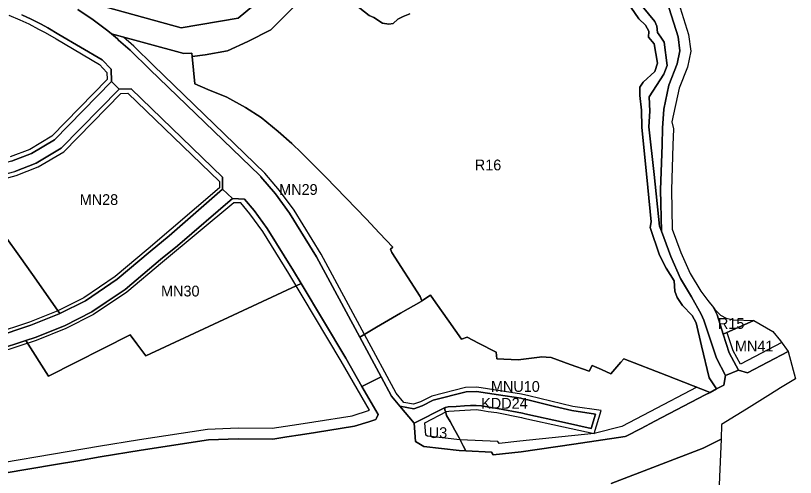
# Model space of a CAD drawing. Extents: x 7440055 to 7442242, y 5549003 to 5552256.
# Drawn here: x 7441405 to 7442129, y 5549663 to 5550092 of the extents above; entities that cross this region are included whole.
import ezdxf

# ---------------------------------------------------------------- set-up
doc = ezdxf.new("R2010")
doc.units = 0
for name, color, linetype in [('linie_rozgraniczajace', 7, 'Continuous'), ('linie_zabudowy_nieprzekraczalne', 7, 'Continuous'), ('oznaczenia_przeznaczen', 7, 'Continuous')]:
    doc.layers.add(name, color=color, linetype=linetype)

msp = doc.modelspace()

# ---------------------------------------------------------------- linework, layer by layer
at = {"layer": 'linie_rozgraniczajace'}
for points in [[(7441674.24, 5550141.39), (7441611.9, 5550089.62), (7441559.01, 5550080.87), (7441481.52, 5550102.04)], [(7441559.01, 5550080.87), (7441611.9, 5550089.62), (7441674.24, 5550141.39)], [(7441692.73, 5550130), (7441642.28, 5550079.02), (7441620.77, 5550068.05), (7441601.87, 5550059.51), (7441581.34, 5550055.76), (7441569.05, 5550054.15), (7441568.76, 5550057.15), (7441561.3, 5550056.89), (7441494.21, 5550075.16), (7441490.83, 5550078.03), (7441477.25, 5550088.28), (7441463.14, 5550097.77)], [(7441972.94, 5550105.02), (7441983.93, 5550089.01), (7441990.13, 5550083.21), (7441993.12, 5550077.7), (7441993.01, 5550072.24), (7441998.22, 5550065.89), (7442001.21, 5550048.12), (7441998.6, 5550040.12), (7441988.07, 5550030.45), (7441984.77, 5550025.7), (7441984.94, 5550018.04), (7441986.35, 5550004.2), (7441986.75, 5549988.5), (7441992.16, 5549932.41), (7441995.23, 5549900.66), (7441994.44, 5549895.25), (7442003.03, 5549869.81), (7442009.41, 5549857.55), (7442016.6, 5549845.99), (7442017.41, 5549836.2), (7442019.5, 5549830.32), (7442024.59, 5549822.88), (7442033.53, 5549813.67), (7442037.16, 5549806.8), (7442042.16, 5549785.37), (7442049.07, 5549755.74), (7442056.11, 5549745.53), (7442050, 5549742.32), (7442010.03, 5549757.96), (7441970.05, 5549773.59), (7441967.06, 5549770.5), (7441957.87, 5549759.65), (7441949.26, 5549763.47), (7441940.66, 5549767.29), (7441937.79, 5549761.95), (7441920.15, 5549768.26), (7441902.51, 5549774.58), (7441897.92, 5549774.87), (7441893.33, 5549775.16), (7441891.75, 5549774.94), (7441871.89, 5549772.55), (7441852.02, 5549773.37), (7441851.51, 5549779.71), (7441835.18, 5549787.99), (7441824.6, 5549793.62), (7441819.19, 5549791.62), (7441807.34, 5549808.48), (7441795.49, 5549825.34), (7441790.46, 5549832.53), (7441782.55, 5549827.29), (7441780.89, 5549831.28), (7441754.71, 5549872.13), (7441753.32, 5549875.41), (7441755.57, 5549877.22), (7441743.16, 5549890.27), (7441730.76, 5549903.32), (7441693.28, 5549942.22), (7441670.71, 5549964.67), (7441661.77, 5549973.45), (7441649.09, 5549984.53), (7441633.37, 5549997.39), (7441618.76, 5550006.86), (7441601.47, 5550016.57), (7441583.79, 5550023.49), (7441571.52, 5550028.92), (7441570.28, 5550041.54), (7441569.05, 5550054.15), (7441581.34, 5550055.76), (7441601.87, 5550059.51), (7441620.77, 5550068.05), (7441642.28, 5550079.02), (7441692.73, 5550130)], [(7441976.67, 5550113.66), (7441998.68, 5550086.75), (7442000.54, 5550082.2), (7442001.11, 5550076.43), (7442004.32, 5550072.02), (7442007.52, 5550067.62), (7442010.34, 5550045.8), (7442007.13, 5550037.86), (7441993.54, 5550016.61), (7441994.23, 5550003.51), (7441993.07, 5549988.97), (7441998.01, 5549944.73), (7442003.2, 5549896.54), (7442005.05, 5549891.87), (7442013.57, 5549868.39), (7442022.72, 5549848.18), (7442032.85, 5549831.05), (7442041.65, 5549815.05), (7442044.4, 5549809.39), (7442055.87, 5549774.01), (7442064.47, 5549758.06), (7442062.89, 5549749.08), (7442056.11, 5549745.53), (7442049.07, 5549755.74), (7442042.16, 5549785.37), (7442037.16, 5549806.8), (7442033.53, 5549813.67), (7442024.59, 5549822.88), (7442019.5, 5549830.32), (7442017.41, 5549836.2), (7442016.6, 5549845.99), (7442009.41, 5549857.55), (7442003.03, 5549869.81), (7441994.44, 5549895.25), (7441995.23, 5549900.66), (7441992.16, 5549932.41), (7441986.75, 5549988.5), (7441986.35, 5550004.2), (7441984.94, 5550018.04), (7441984.77, 5550025.7), (7441988.07, 5550030.45), (7441998.6, 5550040.12), (7442001.21, 5550048.12), (7441998.22, 5550065.89), (7441993.01, 5550072.24), (7441993.12, 5550077.7), (7441990.13, 5550083.21), (7441983.93, 5550089.01), (7441972.94, 5550105.02)], [(7442009.89, 5550105.65), (7442020.35, 5550072.34), (7442022, 5550059.49), (7442019.49, 5550047.24), (7442011.85, 5550027.55), (7442007.09, 5550005.31), (7442005.97, 5549987.77), (7442005.55, 5549972.04), (7442004.11, 5549930.49), (7442005.05, 5549891.87), (7442003.2, 5549896.54), (7441998.01, 5549944.73), (7441993.07, 5549988.97), (7441994.23, 5550003.51), (7441993.54, 5550016.61), (7442007.13, 5550037.86), (7442010.34, 5550045.8), (7442007.52, 5550067.62), (7442004.32, 5550072.02), (7442001.11, 5550076.43), (7442000.54, 5550082.2), (7441998.68, 5550086.75), (7441976.67, 5550113.66)], [(7442019.12, 5550109.63), (7442030.16, 5550074.49), (7442032.13, 5550059.11), (7442029.11, 5550044.41), (7442021.46, 5550024.67), (7442014.53, 5549993.6), (7442015.95, 5549987.13), (7442015.54, 5549971.73), (7442014.83, 5549951.09), (7442014.12, 5549930.44), (7442015, 5549893.75), (7442022.83, 5549872.17), (7442031.61, 5549852.8), (7442041.46, 5549836.15), (7442048, 5549827.75), (7442053.12, 5549821.19), (7442056.49, 5549814.25), (7442062.26, 5549796.46), (7442067.88, 5549779.14), (7442076.54, 5549763.06), (7442064.47, 5549758.06), (7442055.87, 5549774.01), (7442044.4, 5549809.39), (7442041.65, 5549815.05), (7442032.85, 5549831.05), (7442022.72, 5549848.18), (7442013.57, 5549868.39), (7442005.05, 5549891.87), (7442004.11, 5549930.49), (7442005.55, 5549972.04), (7442005.97, 5549987.77), (7442007.09, 5550005.31), (7442011.85, 5550027.55), (7442019.49, 5550047.24), (7442022, 5550059.49), (7442020.35, 5550072.34), (7442009.89, 5550105.65)], [(7441411.06, 5550092.87), (7441419.58, 5550088.95), (7441428.98, 5550084.13), (7441435.04, 5550080.83), (7441445.51, 5550074.75), (7441485.64, 5550051.12), (7441493.91, 5550042.46), (7441494.16, 5550031.09), (7441441.35, 5549976.89), (7441420.1, 5549964.26), (7441401.34, 5549957.05), (7441382.54, 5549951.99), (7441363.61, 5549950.18), (7441351.43, 5549950.16), (7441322.11, 5549991.27), (7441305.11, 5550015.41), (7441288.11, 5550039.55), (7441272.75, 5550061.72), (7441257.4, 5550083.89), (7441244.66, 5550101.57)], [(7441463.14, 5550097.77), (7441477.25, 5550088.28), (7441490.83, 5550078.03), (7441494.21, 5550075.16), (7441499.77, 5550070.46), (7441500.88, 5550069.36), (7441511.72, 5550060.01), (7441529.91, 5550042.11), (7441632, 5549943.59), (7441632.49, 5549943.12), (7441632.97, 5549942.66), (7441633, 5549942.63), (7441633.03, 5549942.59), (7441646.41, 5549926.57), (7441659.68, 5549908.55), (7441684.68, 5549868.19), (7441724.84, 5549793.66), (7441744.73, 5549756.72), (7441726.85, 5549747.85), (7441711.71, 5549773.91), (7441670.25, 5549843.55), (7441663.31, 5549855.21), (7441638.95, 5549894.53), (7441626.73, 5549911.13), (7441617.9, 5549921.71), (7441606.51, 5549922.31), (7441597.49, 5549930.9), (7441597.49, 5549942.15), (7441512.47, 5550024.21), (7441501.33, 5550023.93), (7441494.16, 5550031.09), (7441493.91, 5550042.46), (7441485.64, 5550051.12), (7441445.51, 5550074.75), (7441435.04, 5550080.83), (7441428.98, 5550084.13), (7441419.58, 5550088.95), (7441411.06, 5550092.87)], [(7441481.52, 5550102.04), (7441559.01, 5550080.87)], [(7441771.31, 5550093.94), (7441765.12, 5550091.38), (7441760.26, 5550088.83), (7441755.76, 5550084.91), (7441751.84, 5550084.12), (7441745.89, 5550085.02), (7441737.76, 5550090.54), (7441733.44, 5550092.16), (7441720.4, 5550102.47)], [(7441720.4, 5550102.47), (7441733.44, 5550092.16), (7441737.76, 5550090.54), (7441745.89, 5550085.02), (7441751.84, 5550084.12), (7441755.76, 5550084.91), (7441760.26, 5550088.83), (7441765.12, 5550091.38), (7441771.31, 5550093.94)], [(7441401.34, 5549957.05), (7441420.1, 5549964.26), (7441441.35, 5549976.89), (7441494.16, 5550031.09), (7441501.33, 5550023.93), (7441447.59, 5549968.97), (7441424.48, 5549955.23), (7441404.44, 5549947.53)], [(7441384.91, 5549793.35), (7441419.28, 5549804.6), (7441445.61, 5549815.19), (7441446.19, 5549815.48), (7441470.08, 5549827.43), (7441499.57, 5549847.44), (7441530.17, 5549873.25), (7441547.82, 5549887.51), (7441597.49, 5549930.9), (7441606.51, 5549922.31), (7441555.55, 5549878.33), (7441539.85, 5549865.65), (7441506.83, 5549837.87), (7441489.36, 5549826.01), (7441476.16, 5549817.06), (7441450.54, 5549804.24), (7441423.39, 5549793.32), (7441414.65, 5549790.45), (7441388.23, 5549781.81)], [(7441395.68, 5549887.23), (7441408.82, 5549868.65), (7441420.8, 5549851.6), (7441446.19, 5549815.48), (7441445.61, 5549815.19), (7441419.28, 5549804.6), (7441384.91, 5549793.35)], [(7441388.23, 5549781.81), (7441414.65, 5549790.45), (7441435.92, 5549757.3), (7441511.7, 5549795.71), (7441517.89, 5549787.47), (7441526.2, 5549776.27), (7441670.25, 5549843.55), (7441711.71, 5549773.91), (7441726.85, 5549747.85), (7441741.99, 5549721.79), (7441740.32, 5549718.3), (7441739.77, 5549717.16), (7441733.22, 5549715.09), (7441719.97, 5549710.88), (7441683.7, 5549704.98), (7441669.66, 5549702.95), (7441656.92, 5549700.93), (7441644.19, 5549698.91), (7441611.87, 5549699.24), (7441584.47, 5549698.28), (7441521.94, 5549688.54), (7441483.91, 5549682.43), (7441463.06, 5549678.85), (7441442.22, 5549675.26), (7441394.72, 5549667.37)], [(7441394.72, 5549667.37), (7441442.22, 5549675.26), (7441463.06, 5549678.85), (7441483.91, 5549682.43), (7441521.94, 5549688.54), (7441584.47, 5549698.28), (7441611.87, 5549699.24), (7441644.19, 5549698.91), (7441656.92, 5549700.93), (7441669.66, 5549702.95), (7441683.7, 5549704.98), (7441719.97, 5549710.88), (7441733.22, 5549715.09), (7441739.77, 5549717.16), (7441740.32, 5549718.3), (7441741.99, 5549721.79), (7441726.85, 5549747.85), (7441744.73, 5549756.72), (7441754.33, 5549738.88), (7441762.04, 5549729.6), (7441775.29, 5549713.56), (7441776.39, 5549696.69), (7441784.32, 5549691.97), (7441817.04, 5549688.22), (7441823.32, 5549687.94), (7441847.16, 5549686.89), (7441848.62, 5549684.33), (7441874.77, 5549687.08), (7441923.61, 5549694.24), (7441971.21, 5549701.23), (7441972.08, 5549701.49), (7441985.98, 5549708.77), (7441998.85, 5549715.52), (7442045.37, 5549739.9), (7442050, 5549742.32), (7442056.11, 5549745.53), (7442062.89, 5549749.08), (7442064.47, 5549758.06), (7442076.54, 5549763.06), (7442084.77, 5549760.55), (7442122.42, 5549780.28), (7442129.27, 5549755.01), (7442115.49, 5549746.43), (7442106.1, 5549740.59), (7442083.82, 5549726.72), (7442074.17, 5549720.9), (7442060.76, 5549712.39), (7442060.22, 5549698.83), (7442043.62, 5549690.55), (7441958.36, 5549657.75)], [(7441958.36, 5549657.75), (7442043.62, 5549690.55), (7442060.22, 5549698.83), (7442058.8, 5549663.73), (7442057.24, 5549624.99)]]:
    msp.add_lwpolyline(points, dxfattribs=at)
for points in [[(7441494.21, 5550075.16), (7441561.3, 5550056.89), (7441568.76, 5550057.15), (7441569.05, 5550054.15), (7441570.28, 5550041.54), (7441571.52, 5550028.92), (7441583.79, 5550023.49), (7441601.47, 5550016.57), (7441618.76, 5550006.86), (7441633.37, 5549997.39), (7441649.09, 5549984.53), (7441661.77, 5549973.45), (7441670.71, 5549964.67), (7441693.28, 5549942.22), (7441730.76, 5549903.32), (7441743.16, 5549890.27), (7441755.57, 5549877.22), (7441753.32, 5549875.41), (7441754.71, 5549872.13), (7441780.89, 5549831.28), (7441782.55, 5549827.29), (7441781.82, 5549826.81), (7441762.61, 5549815.72), (7441740.2, 5549802.86), (7441724.84, 5549793.66), (7441684.68, 5549868.19), (7441659.68, 5549908.55), (7441646.41, 5549926.57), (7441633.03, 5549942.59), (7441633, 5549942.63), (7441632.97, 5549942.66), (7441632.49, 5549943.12), (7441632, 5549943.59), (7441529.91, 5550042.11), (7441511.72, 5550060.01), (7441500.88, 5550069.36), (7441499.77, 5550070.46)], [(7441358.42, 5549940.18), (7441364.1, 5549940.19), (7441384.33, 5549942.11), (7441404.44, 5549947.53), (7441424.48, 5549955.23), (7441447.59, 5549968.97), (7441501.33, 5550023.93), (7441512.47, 5550024.21), (7441597.49, 5549942.15), (7441597.49, 5549930.9), (7441547.82, 5549887.51), (7441530.17, 5549873.25), (7441499.57, 5549847.44), (7441470.08, 5549827.43), (7441446.19, 5549815.48), (7441420.8, 5549851.6), (7441408.82, 5549868.65), (7441395.68, 5549887.23), (7441382.53, 5549905.82)], [(7441414.65, 5549790.45), (7441423.39, 5549793.32), (7441450.54, 5549804.24), (7441476.16, 5549817.06), (7441489.36, 5549826.01), (7441506.83, 5549837.87), (7441539.85, 5549865.65), (7441555.55, 5549878.33), (7441606.51, 5549922.31), (7441617.9, 5549921.71), (7441626.73, 5549911.13), (7441638.95, 5549894.53), (7441663.31, 5549855.21), (7441670.25, 5549843.55), (7441526.2, 5549776.27), (7441517.89, 5549787.47), (7441511.7, 5549795.71), (7441435.92, 5549757.3)], [(7441724.84, 5549793.66), (7441740.2, 5549802.86), (7441762.61, 5549815.72), (7441781.82, 5549826.81), (7441782.55, 5549827.29), (7441790.46, 5549832.53), (7441795.49, 5549825.34), (7441807.34, 5549808.48), (7441819.19, 5549791.62), (7441824.6, 5549793.62), (7441835.18, 5549787.99), (7441851.51, 5549779.71), (7441852.02, 5549773.37), (7441871.89, 5549772.55), (7441891.75, 5549774.94), (7441893.33, 5549775.16), (7441897.92, 5549774.87), (7441902.51, 5549774.58), (7441920.15, 5549768.26), (7441937.79, 5549761.95), (7441940.66, 5549767.29), (7441949.26, 5549763.47), (7441957.87, 5549759.65), (7441967.06, 5549770.5), (7441970.05, 5549773.59), (7442010.03, 5549757.96), (7442050, 5549742.32), (7442045.37, 5549739.9), (7441998.85, 5549715.52), (7441985.98, 5549708.77), (7441972.08, 5549701.49), (7441971.21, 5549701.23), (7441923.61, 5549694.24), (7441874.77, 5549687.08), (7441848.62, 5549684.33), (7441847.16, 5549686.89), (7441823.32, 5549687.94), (7441820.79, 5549692.75), (7441816.95, 5549700.05), (7441813.1, 5549707.34), (7441808.7, 5549715.11), (7441805.46, 5549720.8), (7441804.64, 5549723.51), (7441803.82, 5549726.22), (7441803.89, 5549727.2), (7441803.95, 5549728.18), (7441806.73, 5549728.94), (7441814.42, 5549729.33), (7441822.11, 5549729.71), (7441827.52, 5549729.99), (7441832.93, 5549730.26), (7441837.76, 5549729.86), (7441841.28, 5549729.16), (7441844.81, 5549728.45), (7441852.57, 5549727.42), (7441875.86, 5549723), (7441878.06, 5549722.3), (7441914.84, 5549714.19), (7441939.71, 5549708.72), (7441943.65, 5549722.12), (7441921.75, 5549725.37), (7441905.59, 5549729.27), (7441880.8, 5549735.26), (7441877.53, 5549736.04), (7441874.26, 5549736.83), (7441853.74, 5549739.91), (7441833.22, 5549742.98), (7441823.63, 5549742.8), (7441793.09, 5549735.04), (7441782.7, 5549729.87), (7441775.04, 5549727.15), (7441762.04, 5549729.6), (7441754.33, 5549738.88), (7441744.73, 5549756.72)], [(7442053.12, 5549821.19), (7442054.55, 5549819.35), (7442059.77, 5549813.9), (7442064.94, 5549811.12), (7442071.85, 5549809.55), (7442090.8, 5549809.16), (7442062.26, 5549796.46), (7442056.49, 5549814.25)], [(7442062.26, 5549796.46), (7442090.8, 5549809.16), (7442108.2, 5549798.8), (7442115.46, 5549790.27), (7442122.42, 5549780.28), (7442084.77, 5549760.55), (7442076.54, 5549763.06), (7442067.88, 5549779.14)], [(7441762.04, 5549729.6), (7441775.04, 5549727.15), (7441782.7, 5549729.87), (7441793.09, 5549735.04), (7441823.63, 5549742.8), (7441833.22, 5549742.98), (7441853.74, 5549739.91), (7441874.26, 5549736.83), (7441877.53, 5549736.04), (7441880.8, 5549735.26), (7441905.59, 5549729.27), (7441921.75, 5549725.37), (7441943.65, 5549722.12), (7441939.71, 5549708.72), (7441914.84, 5549714.19), (7441878.06, 5549722.3), (7441875.86, 5549723), (7441852.57, 5549727.42), (7441844.81, 5549728.45), (7441841.28, 5549729.16), (7441837.76, 5549729.86), (7441832.93, 5549730.26), (7441827.52, 5549729.99), (7441822.11, 5549729.71), (7441814.42, 5549729.33), (7441806.73, 5549728.94), (7441803.95, 5549728.18), (7441775.29, 5549713.56)], [(7441775.29, 5549713.56), (7441803.95, 5549728.18), (7441803.89, 5549727.2), (7441803.82, 5549726.22), (7441804.64, 5549723.51), (7441805.46, 5549720.8), (7441808.7, 5549715.11), (7441813.1, 5549707.34), (7441816.95, 5549700.05), (7441820.79, 5549692.75), (7441823.32, 5549687.94), (7441817.04, 5549688.22), (7441784.32, 5549691.97), (7441776.39, 5549696.69)]]:
    msp.add_lwpolyline(points, close=True, dxfattribs=at)
at = {"layer": 'linie_zabudowy_nieprzekraczalne'}
for points in [[(7441399, 5550092.55), (7441409.04, 5550088.3), (7441417.39, 5550084.45), (7441426.64, 5550079.71), (7441432.58, 5550076.47), (7441442.98, 5550070.44), (7441483.1, 5550046.81), (7441489.98, 5550039.34), (7441490.13, 5550032.68), (7441438.86, 5549980.06), (7441418.35, 5549967.87), (7441400.1, 5549960.86)], [(7442037.66, 5549747.15), (7441994.21, 5549724.38), (7441968.18, 5549710.73), (7441942.5, 5549704.01), (7441873.52, 5549697), (7441854.07, 5549694.96), (7441853.11, 5549696.64), (7441817.83, 5549698.19), (7441787.59, 5549701.66), (7441786.03, 5549702.59), (7441785.27, 5549714.16), (7441805.4, 5549724.43), (7441807.37, 5549724.97), (7441822.31, 5549725.72), (7441832.86, 5549726.25), (7441837.2, 5549725.89), (7441844.15, 5549724.51), (7441851.93, 5549723.47), (7441874.88, 5549719.11), (7441877.02, 5549718.43), (7441913.98, 5549710.29), (7441942.5, 5549704.01), (7441948.78, 5549725.4), (7441922.52, 5549729.3), (7441881.74, 5549739.14), (7441875.03, 5549740.76), (7441833.48, 5549746.99), (7441823.1, 5549746.79), (7441791.69, 5549738.81), (7441781.13, 5549733.56), (7441774.72, 5549731.28), (7441765.56, 5549732.78), (7441758.52, 5549741.64), (7441729.24, 5549796.04), (7441689.01, 5549870.69), (7441663.82, 5549911.35), (7441650.35, 5549929.65), (7441636.7, 5549946), (7441533.4, 5550045.69), (7441515.11, 5550063.69), (7441505.36, 5550072.13)], [(7441385.04, 5549938.16), (7441405.68, 5549943.72), (7441426.23, 5549951.62), (7441450.09, 5549965.8), (7441503.06, 5550019.97), (7441509.49, 5550020.13), (7441594.44, 5549938.15), (7441594.49, 5549932.28), (7441528.23, 5549875.53), (7441497.76, 5549849.84), (7441468.56, 5549830.03), (7441444.38, 5549817.93), (7441418.25, 5549807.42), (7441384.08, 5549796.23)], [(7441393.09, 5549677.24), (7441440.55, 5549685.12), (7441482.27, 5549692.3), (7441520.38, 5549698.42), (7441583.52, 5549708.25), (7441611.74, 5549709.24), (7441643.45, 5549708.92), (7441668.16, 5549712.84), (7441682.19, 5549714.86), (7441717.64, 5549720.63), (7441733.88, 5549725.79), (7441707.4, 5549771.37), (7441659.04, 5549852.61), (7441634.81, 5549891.73), (7441622.8, 5549908.05), (7441614.21, 5549918.28), (7441607.97, 5549918.3), (7441541.78, 5549863.35), (7441508.64, 5549835.47), (7441477.68, 5549814.46), (7441451.77, 5549801.51), (7441424.42, 5549790.5), (7441389.06, 5549778.93)], [(7442116.66, 5549788.55), (7442078.2, 5549768.4), (7442071.57, 5549780.72), (7442066.06, 5549797.7)]]:
    msp.add_lwpolyline(points, dxfattribs=at)

# ---------------------------------------------------------------- texts
at = {"layer": 'oznaczenia_przeznaczen'}
for s, p in [('R16', (7441831.64, 5549948.46)), ('MN29', (7441649.97, 5549925.69)), ('MN28', (7441464.78, 5549916.29)), ('MN30', (7441540.32, 5549831.37)), ('R15', (7442057.36, 5549801.3)), ('MN41', (7442073.15, 5549780.26)), ('MNU10', (7441846.6, 5549742.79)), ('KDD24', (7441837.56, 5549727.16)), ('U3', (7441788.89, 5549699.91))]:
    msp.add_text(s, height=10, dxfattribs=at).set_placement(p)

doc.saveas('drawing.dxf')
